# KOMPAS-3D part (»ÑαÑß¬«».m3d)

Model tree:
1. Эскиз:1
2. Операция выдавливания:1
     Расстояние 1 = 4; Расстояние 2 = 1
3. Эскиз:2
4. Вырезать элемент выдавливания:1
     Расстояние 1 = 0.5
5. Эскиз:3
6. Вырезать элемент выдавливания:2
     Расстояние 1 = 7
7. Эскиз:4
8. Вырезать элемент выдавливания:3
     Расстояние 1 = 7
9. Скругление:1
     Радиус = 0.5

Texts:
  Сплав АЛ8  ГОСТ 1583-93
